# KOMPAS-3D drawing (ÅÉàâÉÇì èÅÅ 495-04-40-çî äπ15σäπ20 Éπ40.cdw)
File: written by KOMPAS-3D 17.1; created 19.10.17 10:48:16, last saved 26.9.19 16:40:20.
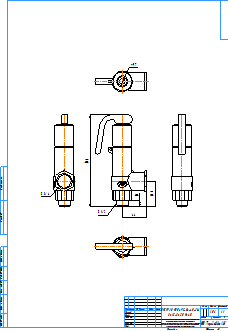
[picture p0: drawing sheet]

Sheet 1: A2, portrait

Title block, sheet 1: name: ПРЕГРАН КПП 495-04-40-ЗМ / Ду15хДу20 Ру40; material: Сталь 20  ГОСТ 1050-2013; mass: 1,06; sheets: 1; sheet format: A2; stored path: C:\Users\kka\KOMPAS_Work\!Trash\Прегран КПП 495\ПРЕГРАН КПП 495-04-40-ЗМ\KOMPAS 2D\Прегран КПП 495 Ду15хДу20 Ру40.cdw

Views: Спереди 6, Проекционный вид 7, Проекционный вид 8, Проекционный вид 9, Проекционный вид 10
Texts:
  kka
  adl
  Рама для чертежей
  Лит-Масса-Масштаб
  Материал-Предприятие
  Масштаб
  Изм.
  Лист
  № докум.
  Подп.
  Дата
  Лит.
  Разраб.
  Пров.
  Т.контр.
  Листов
  Внимание! Данный продукт является объектом авторского права ООО «Торговый Дом АДЛ».
  Запрещается изменение, копирование, распространение
  (в том числе путем копирования на другие сайты и ресурсы в Интернете)
  или любое иное использование информации и объектов без предварительного
  согласия правообладателя (ООО «Торговый Дом АДЛ»).
  Н.контр.
  Утв.
  ООО "Торговый дом АДЛ"
  Изменение
  Номер документа
  Подпись
  Обозначение документа
  Наименование изделия
  Масса изделия по ГОСТ 2.109-73
  Порядковый номер листа
  Общее количество листов в документе
  Характер работы, выполненной лицом, подписавшим документ
  Наименование или индекс предприятия, выпускающего документ
  Инв. № подл.
  Подп. и дата
  Взам. инв. №
  Инв. № дубл.
  Инвентарный номер подлинника по ГОСТ 2.501-68
  Подпись принявшего подлинник в отдел технической документации
  Инвентарный номер подлинника, взамен которого выпущен данный подлинник
  Инвентарный номер дубликата по ГОСТ 2.502-68
  Подпись принявшего дубликат в отдел технической документации
  Справ. №
  Перв. примен.
  Обозначение документа, взамен или на основании которого выпущен данный документ
  Обозначение документа, в котором впервые записан данный документ
  Подпись лица, копировавшего чертеж
  Обозначение формата листа
  !Рама для чертежа
Dimensions and other numbers on the sheet: 45,5; 12; 44; 164; 9,7; 1,06; 1:1; 1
